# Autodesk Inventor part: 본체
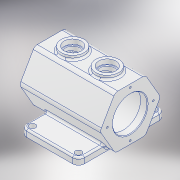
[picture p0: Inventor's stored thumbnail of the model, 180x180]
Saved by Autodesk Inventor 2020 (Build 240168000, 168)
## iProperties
Created: 2021-06
Part Number: 본체
Material: 알루미늄 6061
Document SubType Name: Modeling
Designer: MIRAE
Density: 2.7 g/cm^3
Appearance: 알루미늄 - 평지
Mass: 1495.28 g
Surface Area: 1102.35 cm^2
Volume: 553.807 cm^3
Author: MIRAE
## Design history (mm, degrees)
sketch "스케치1" dims "d0" = 105
  geometry: L1 (95.466, -26.25)-(50, -52.5); L2 (50, -52.5)-(4.534, -26.25); L3 (4.534, -26.25)-(4.534, 26.25); L4 (4.534, 26.25)-(50, 52.5); L5 (50, 52.5)-(95.466, 26.25); L6 (95.466, 26.25)-(95.466, -26.25); 4 further points
  constraints: 12 end point, 1 coincident, 1 horizontal alignment, 1 midpoint, 1 vertical, 16 other
  dimensions: "d1" = 50 distance of point (0, 0) point (50, 0)
extrude "돌출1" new body sketch "스케치1" stored distance "d2" = 140; taper "d3" = 0 deg
sketch "스케치2"
  geometry: L1 (-70, 50)-(-70, 4.534) reference; L2 (-70, 50)-(70, 50); L3 (-70, 50)-(-70, 80); L4 (-70, 95.466)-(-70, 50) reference; L5 (-70, 80)-(-58, 80); L6 (-58, 80)-(-58, 87.5); L7 (-58, 87.5)-(58, 87.5); L8 (58, 87.5)-(58, 80); L9 (58, 80)-(70, 80); L10 (70, 50)-(70, 95.466) reference; L11 (70, 4.534)-(70, 50) reference; L12 (70, 80)-(70, 50); 2 further points
  constraints: 16 end point, 3 perpendicular, 3 point on line, 2 collinear, 2 horizontal
  dimensions: "d4" = 60 diameter of L9 L2; "d5" = 75 diameter of L7 L2; "d6" = 12 distance between parallel lines of L6 L3; "d7" = 140 distance of L1.start L2.end
revolve "회전1" sketch "스케치2" stored, may be unused: angle "d8" = 90 deg
sketch "스케치3"
  geometry: L1 (0, 90)-(0, 50); L2 (0, 50)-(-28.284, 78.284); C1 r 30 at (0, 50) reference; C2 r 30 at (0, 50) reference; A1 r 40 centre (0, 50) between (0, 90) and (-28.284, 78.284); 2 further points
  constraints: 4 end point, 2 coincident, 2 point on circle, 1 centre point, 1 vertical
  dimensions: "d9" = 80 diameter of A1; "d10" = 45 deg angle of L2 L1
hole "구멍1" sketch "스케치3" at (-28.284, 78.284) diameter "d11" = 3.242; stored, may be unused: countersink angle "d15" = 90 deg, drill point angle "d17" = 120 deg; dims "d12" = 8, "d13" = 4, "d14" = 2, "d16" = 10
sketch "스케치4" dims "d21" = 80
  geometry: C1 r 30 at (0, 50) reference; 3 further points
  constraints: 2 vertical alignment, 1 coincident, 2 other
hole "구멍2" sketch "스케치4" at (0, 90) diameter "d22" = 3.242; stored, may be unused: countersink angle "d26" = 90 deg, drill point angle "d28" = 120 deg; dims "d23" = 8, "d24" = 4, "d25" = 2, "d27" = 10
node "작업 평면1"
sketch "스케치5"
  geometry: L1 (70, 26.25)-(70, -26.25) reference; C1 r 20 at (30, 0); C2 r 20 at (-30, 0); 1 further point
  constraints: 2 centre point, 2 horizontal alignment
  dimensions: "d33" = 40 diameter of C1; "d34" = 40 diameter of C2; "d35" = 40 distance from line of C1.centre L1; "d36" = 60 distance of C2.centre C1.centre
extrude "돌출2" join sketch "스케치5" stored distance "d37" = 0; taper "d38" = 0 deg
sketch "스케치6"
  geometry: C1 r 20 at (0, 0) reference; C2 r 20 at (60, 0) reference; 3 further points
  constraints: 2 coincident
hole "구멍3" sketch "스케치6" at (0, 0), (60, 0) diameter "d39" = 25; stored, may be unused: countersink angle "d43" = 90 deg, drill point angle "d45" = 0 deg; dims "d40" = 8, "d41" = 30, "d42" = 8, "d44" = 28.5
node "작업 평면2"
sketch "스케치7"
  geometry: L1 (-45, 12)-(55, 12); L2 (55, 12)-(55, 0); L3 (55, 0)-(-45, 0); L4 (-45, 0)-(-45, 12); L5 (-70, 50)-(70, 50) reference; L6 (-70, 4.534)-(-70, 50) reference; 1 further point
  constraints: 8 end point, 2 parallel, 1 horizontal, 1 perpendicular
  dimensions: "d47" = 50 distance between parallel lines of L3 L5; "d48" = 12 distance between parallel lines of L3 L1; "d49" = 25 distance between parallel lines of L4 L6; "d50" = 100 distance between parallel lines of L2 L4
extrude "돌출3" join sketch "스케치7" distance "d51" = 150; taper "d52" = 0 deg
fillet "모깎기1" dims "d53" = 10
sketch "스케치8"
  geometry: A1 r 10 centre (10, 34.439) between (10, 44.439) and (0, 34.439) reference; A2 r 10 centre (90, 34.439) between (100, 34.439) and (90, 44.439) reference; A3 r 10 centre (90, -95.561) between (90, -105.561) and (100, -95.561) reference; A4 r 10 centre (10, -95.561) between (0, -95.561) and (10, -105.561) reference; 5 further points
  constraints: 4 coincident
hole "구멍4" sketch "스케치8" at (10, 34.439), (90, 34.439), (90, -95.561), (10, -95.561) diameter "d54" = 11; stored, may be unused: countersink angle "d58" = 90 deg, drill point angle "d60" = 0 deg; dims "d55" = 8, "d56" = 30, "d57" = 8, "d59" = 28.5
fillet "모깎기2" dims "d61" = 8
fillet "모깎기3" dims "d62" = 5
fillet "모깎기4" dims "d63" = 3
fillet "모깎기5" dims "d64" = 3
fillet "모깎기6" dims "d65" = 3
chamfer "모따기1" distance "d66" = 1; stored, may be unused: second distance "d67" = 2, angle "d68" = 45 deg
sketch "스케치9"
  geometry: L1 (-10, -7)-(-10, -39.707) reference; L2 (80, 3)-(0, 3) reference; 2 further points
  constraints: 1 other
  dimensions: "d69" = 50 distance from line of point (40, -11) L1; "d70" = 14 distance from line of point (40, -11) L2
feature "엠보싱1" sketch "스케치9" dims "d4" = 60, "d5" = 75, "d6" = 12, "d7" = 140, "d71" = 0.5, "d72" = 0
node "솔리드1"
pattern_circular "원형 패턴1" dims angle "d19" = 360 deg
pattern_circular "원형 패턴2" dims angle "d30" = 360 deg
feature "A9D066F2-1C7D-4E18-AEED-F7BC21143FA4" dims "d39" = 25, "d40" = 8, "d41" = 30, "d42" = 8, "d43" = 90 deg, "d44" = 28.5, "d45" = 0
other parameters: "d32" = 102.5, "d46" = 75
